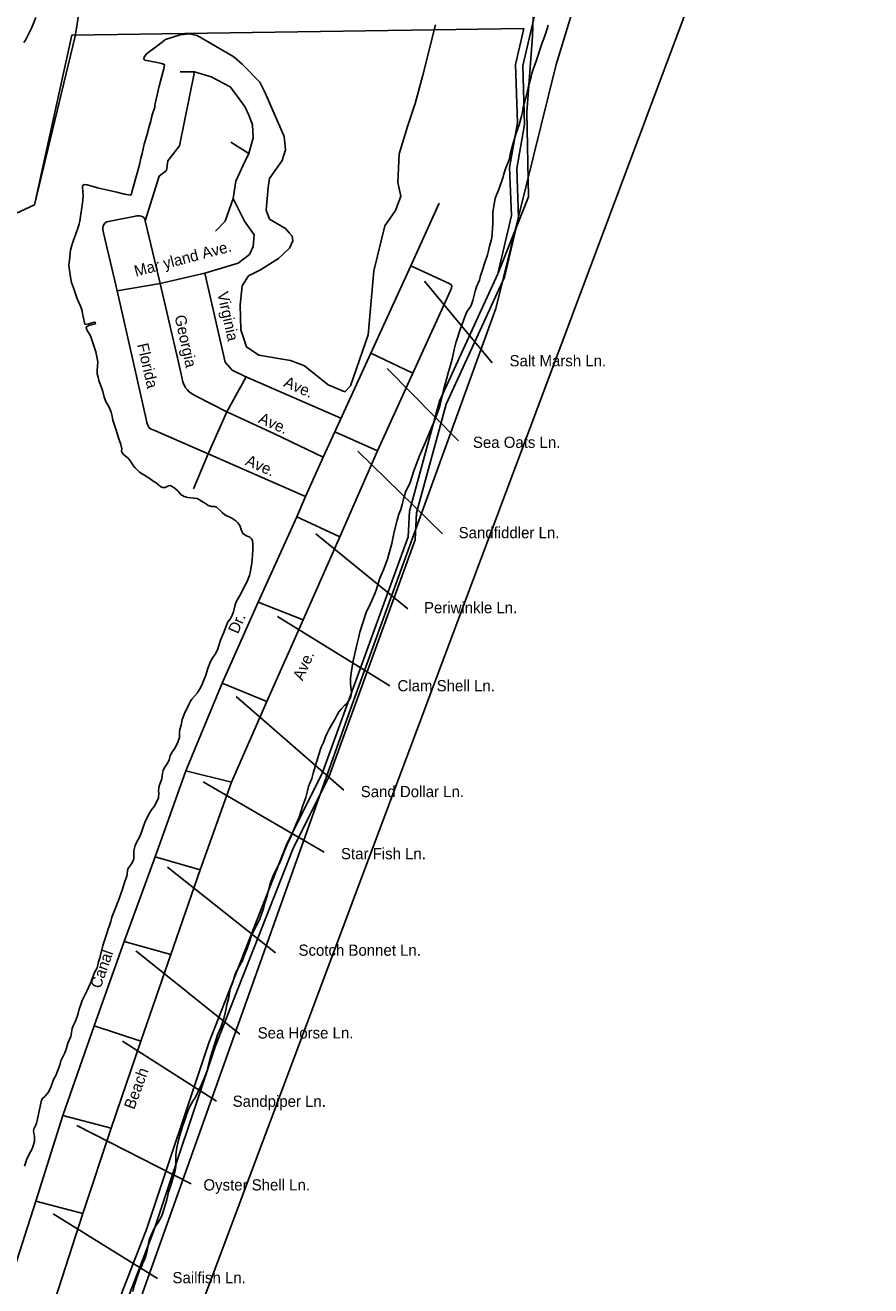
# Model space of a CAD drawing. Extents: x 1945482 to 2853149, y 66427 to 1015778.
# Drawn here: x 2336264 to 2341217, y 107724 to 115103 of the extents above; entities that cross this region are included whole.
import ezdxf

# ---------------------------------------------------------------- set-up
doc = ezdxf.new("R2010")
doc.units = 0
for name, color, linetype in [('Old_Level_10', 7, 'Continuous'), ('Old_Level_35', 7, 'Continuous'), ('Old_Level_48', 7, 'Continuous'), ('Old_Level_49', 7, 'Continuous'), ('Old_Level_52', 7, 'Continuous'), ('Old_Level_60', 7, 'Continuous'), ('Old_Level_61', 7, 'Continuous'), ('Old_Level_63', 7, 'Continuous')]:
    doc.layers.add(name, color=color, linetype=linetype)

msp = doc.modelspace()

# ---------------------------------------------------------------- linework, layer by layer
at = {"layer": 'Old_Level_10'}
for points in [[(2338998.7, 113127.3), (2338603.3, 113605.7)], [(2338801, 112671), (2338383.6, 113094.4)], [(2338707.6, 112126.7), (2338213.3, 112610.5)], [(2338504.4, 111686.9), (2337966.1, 112126.7)], [(2338400, 111236.1), (2337740.9, 111642.9)], [(2338130.7, 110624.6), (2337499.2, 111173.9)], [(2338015.4, 110262), (2337307, 110674)], [(2337729.8, 109674.2), (2337098.3, 110174.1)], [(2337521.2, 109196.3), (2336911.6, 109685.2)], [(2337383.9, 108805.1), (2336834.8, 109156.6)], [(2337235.6, 108321.7), (2336565.8, 108662.3)], [(2337038, 107767), (2336428.5, 108146)]]:
    msp.add_lwpolyline(points, dxfattribs=at)
at = {"layer": 'Old_Level_35'}
for p, q in [((2338689.3, 114062), (2338523, 113694.1)), ((2338523, 113694.1), (2338288.4, 113183.6)), ((2336802, 113548.3), (2337053.7, 113591.1)), ((2338076.8, 112723.3), (2338288.4, 113183.6)), ((2338288.4, 113183.6), (2338535.3, 113066.3)), ((2338328.4, 112611.8), (2338535.3, 113066.3)), ((2337336.2, 112593.6), (2337445.6, 112840.8)), ((2338076.8, 112723.3), (2338008.5, 112574.5)), ((2338076.8, 112723.3), (2338328.4, 112611.8)), ((2338107.3, 112109.4), (2338328.4, 112611.8)), ((2337250.1, 112388.7), (2337336.2, 112593.6)), ((2337905, 112345.3), (2337336.2, 112593.6)), ((2337905, 112345.3), (2338008.5, 112574.5)), ((2337854.3, 112224.8), (2337905, 112345.3)), ((2337629.4, 111726.2), (2337854.3, 112224.8)), ((2337854.3, 112224.8), (2338107.3, 112109.4)), ((2338107.3, 112109.4), (2337892.5, 111623.1)), ((2337418.1, 111251.8), (2337629.4, 111726.2)), ((2337629.4, 111726.2), (2337892.5, 111623.1)), ((2337892.5, 111623.1), (2337679.6, 111144.6)), ((2337205.7, 110737.7), (2337418.1, 111251.8)), ((2337418.1, 111251.8), (2337679.6, 111144.6)), ((2337679.6, 111144.6), (2337472.1, 110672.4)), ((2337024.9, 110235.6), (2337205.7, 110737.7)), ((2337205.7, 110737.7), (2337472.1, 110672.4)), ((2337472.1, 110672.4), (2337289.6, 110158.4)), ((2336844, 109739.7), (2337024.9, 110235.6)), ((2337024.9, 110235.6), (2337289.6, 110158.4)), ((2337289.6, 110158.4), (2337116.7, 109664.5)), ((2336668.8, 109245.7), (2336844, 109739.7)), ((2336844, 109739.7), (2337116.7, 109664.5)), ((2337116.7, 109664.5), (2336942.2, 109156.4)), ((2336484.7, 108721.9), (2336668.8, 109245.7)), ((2336942.2, 109156.4), (2336668.8, 109245.7)), ((2336942.2, 109156.4), (2336767.3, 108646.7)), ((2336325.6, 108220), (2336484.7, 108721.9)), ((2336484.7, 108721.9), (2336767.3, 108646.7)), ((2336767.3, 108646.7), (2336602.6, 108146.9)), ((2336166.8, 107720.1), (2336325.6, 108220)), ((2336602.6, 108146.9), (2336325.6, 108220)), ((2336602.6, 108146.9), (2336439.8, 107646.8))]:
    msp.add_line(p, q, dxfattribs=at)
for points in [[(2337256.4, 114831), (2337167.3, 114398.1), (2337099.5, 114308.9), (2337091, 114253.8), (2337048.6, 114219.8), (2336966.3, 113957.5)], [(2337053.7, 113591.1), (2337315.8, 113651.1), (2337510.9, 113710.5), (2337578.7, 113761.5), (2337599.9, 113808.2), (2337604.2, 113876.1), (2337549, 113956.7), (2337481.2, 114088.3), (2337498.1, 114190.1), (2337540.6, 114283.5), (2337574.5, 114351.4), (2337599.9, 114444.8), (2337595.7, 114521.1), (2337574.5, 114576.3), (2337553.3, 114623), (2337506.6, 114686.7), (2337464.2, 114741.8), (2337353.9, 114801.3), (2337256.4, 114831), (2337171.6, 114831)], [(2337574.5, 114351.4), (2337468.5, 114419.3)], [(2337481.2, 114088.3), (2337434.5, 113956.7), (2337379.4, 113897.3)], [(2336802, 113548.3), (2336722.6, 113887.5), (2336718.2, 113907.7), (2336717.9, 113916.6), (2336720, 113927.5), (2336724, 113935.8), (2336731.8, 113945.7), (2336741.7, 113952.3), (2336919.5, 113987.5), (2336933.3, 113987.7), (2336943.6, 113985.9), (2336953.6, 113982), (2336958.3, 113978.2), (2336964, 113968), (2336966.3, 113957.5), (2337053.7, 113591.1)], [(2337315.8, 113651.1), (2337434.5, 113131.7), (2337476.9, 113085), (2337553.3, 113046.8)], [(2338535.3, 113066.3), (2338754.4, 113550.6), (2338761.1, 113564.9), (2338762.6, 113576.8), (2338756.3, 113586.4), (2338747.9, 113590.4), (2338523, 113694.1)], [(2337053.7, 113591.1), (2337160.5, 113138.1), (2337181.3, 113042.1), (2337187.6, 113016.1), (2337191.7, 113004.1), (2337198.2, 112990.2), (2337203.8, 112981.3), (2337212.1, 112970.4), (2337225.1, 112957.5), (2337244.3, 112942.8), (2337264.5, 112931.2), (2337445.6, 112840.8)], [(2337336.2, 112593.6), (2337026.7, 112728.5), (2337008.6, 112736.3), (2336998.9, 112741.5), (2336990.8, 112747.4), (2336986.3, 112754.1), (2336980.2, 112766), (2336976.1, 112778), (2336972.4, 112796.9), (2336887.8, 113169), (2336802, 113548.3)], [(2337445.6, 112840.8), (2337558.4, 113044.5)], [(2337553.3, 113046.8), (2338113.1, 112802.2)], [(2337445.6, 112840.8), (2337725.1, 112711.7), (2338008.5, 112574.5)]]:
    msp.add_lwpolyline(points, dxfattribs=at)
at = {"layer": 'Old_Level_48'}
for points in [[(2334660.6, 113382.2), (2335533.7, 113689.2), (2336319, 114052.8), (2336537.9, 115045.8), (2339183.9, 115083.5)], [(2339183.9, 115083.5), (2339135, 114873.3), (2339147.1, 114532.4), (2339100.2, 114271.3), (2339112.1, 113989.4), (2339032.1, 113648.2), (2338690.1, 112902.8), (2338514.1, 112259.1), (2338507.1, 112107.8), (2338005, 110729.2), (2337793.2, 110300.7), (2337339.2, 109147.1)], [(2337339.2, 109147.1), (2336976, 108059.5), (2336830, 107682.8), (2336669.1, 107164.5), (2335564, 103786.1), (2335393, 103428.2), (2334965.1, 102180.4), (2334744.9, 101485.2)]]:
    msp.add_lwpolyline(points, dxfattribs=at)
at = {"layer": 'Old_Level_49'}
for points in [[(2336580.4, 115183.5), (2339245, 115328.5), (2339235.7, 115038.5), (2339203, 114594.1), (2339212.3, 114098.3), (2339032.1, 113648.2), (2338690.1, 112902.8), (2338514.1, 112259.1), (2338507.1, 112107.8), (2338005, 110729.2), (2337793.2, 110300.7), (2337339.2, 109147.1)], [(2334989.1, 113572), (2335533.7, 113689.2), (2336319, 114052.8), (2336557, 115038.5), (2336580.4, 115183.5)], [(2337339.2, 109147.1), (2336976, 108059.5), (2336830, 107682.8), (2336669.1, 107164.5), (2335564, 103786.1), (2335393, 103428.2), (2334965.1, 102180.4), (2334736.2, 101306.7)]]:
    msp.add_lwpolyline(points, dxfattribs=at)
at = {"layer": 'Old_Level_52'}
msp.add_lwpolyline([(2332774.3, 94909.4), (2333577.6, 97883.8), (2334423, 100131.9), (2335251.5, 102714.6), (2335953.9, 104717.9), (2336921.3, 107598.4), (2338178.9, 111127.7), (2339020, 113445.2), (2339373.3, 114873.2), (2339983.2, 116868.4), (2341036.1, 119166.1)], dxfattribs=at)
at = {"layer": 'Old_Level_60'}
for points in [[(2336327.2, 115147.7), (2336303.5, 115090.5), (2336274, 115031.4), (2336265.5, 115015.8), (2336256.2, 115002.1)], [(2338667.2, 115105.9), (2338591, 114803.5), (2338548.5, 114644.4), (2338506, 114517.1), (2338455.2, 114350), (2338446.7, 114182.9), (2338463.7, 114103.3), (2338433, 114017.8), (2338370.2, 113928.3), (2338306.7, 113665.7), (2338272.7, 113291.8), (2338169.7, 112991.4), (2338137, 112957.6), (2338038.2, 112997.4), (2337899.5, 113108.8), (2337817.7, 113140.6), (2337633.2, 113172.4), (2337560, 113220.2), (2337527, 113319.6), (2337522.7, 113466.8), (2337534.5, 113578.2), (2337571.7, 113635.9), (2337641.7, 113671.7), (2337746.7, 113737.3), (2337811.2, 113799), (2337831.5, 113840.8), (2337828.2, 113868.6), (2337812.5, 113886.5), (2337789, 113912.4), (2337695.7, 113968.1), (2337674.5, 114019.8), (2337687.2, 114153.1), (2337695.7, 114206.8), (2337770, 114312.2), (2337789, 114373.9), (2337780.5, 114451.4), (2337670.2, 114708), (2337638.5, 114769.7), (2337534.5, 114875.1), (2337485.7, 114918.9), (2337271.5, 115042.2), (2337224.7, 115052.1), (2337171.7, 115046.2), (2337085, 115020.1), (2337080.2, 115016.1), (2337066.5, 115003.5), (2337011.2, 114962.5), (2336989.5, 114947.9), (2336973.2, 114933.2), (2336961, 114915.3), (2336958.5, 114909.3), (2336960, 114903.3), (2336965, 114898.8), (2337037.7, 114884.5), (2337062.7, 114878.7), (2337079.2, 114873.4), (2337076, 114848.6), (2337071.5, 114833.6), (2337049.7, 114746.9), (2337031.7, 114669.5), (2337027, 114653.8), (2337024, 114636.4), (2337023, 114622.7), (2337010, 114584.2), (2337002, 114556.1), (2336999, 114540.9), (2336994.7, 114525), (2336989.7, 114510), (2336976, 114458.2), (2336961.2, 114406.8), (2336949.5, 114352), (2336941.5, 114324.3)], [(2338879, 113469.3), (2338886.7, 113490.9), (2338899, 113545.9), (2338908, 113571.3), (2338916, 113588.5), (2338924, 113611.6), (2338931.5, 113638.1), (2338940.5, 113663.5), (2338952.2, 113702.4), (2338971, 113758.7), (2338976.7, 113783), (2338984, 113809.1), (2338994.2, 113842.2), (2338997.5, 113860.9), (2339002.5, 113939.6), (2339003, 114008.6), (2339016.5, 114088.7), (2339021.7, 114105.4), (2339035.5, 114136.8), (2339041.7, 114153.3), (2339061, 114209.8), (2339071, 114244.6), (2339079.5, 114268.6), (2339089.7, 114292.6), (2339100.5, 114321), (2339104.7, 114346.9), (2339118, 114398.9), (2339140, 114470.9), (2339147, 114492.3), (2339157.5, 114519.7), (2339171.2, 114571.5), (2339176.7, 114594.7), (2339180.2, 114621.9), (2339182.7, 114631.6), (2339188.5, 114648.1), (2339192.2, 114665.1), (2339209, 114724.2), (2339212.7, 114746), (2339223.2, 114784.7), (2339232, 114820.8), (2339237.5, 114839.6), (2339256.7, 114892.9), (2339291.2, 115000), (2339305.5, 115035), (2339320.5, 115082.5), (2339327.7, 115104.3)], [(2336941.5, 114324.3), (2336934.5, 114288.2), (2336919.7, 114238), (2336891, 114133.1), (2336886, 114116.3), (2336882.2, 114109), (2336846.5, 114114.9), (2336800.2, 114126.3), (2336713, 114145), (2336688.5, 114150.9), (2336627.5, 114168.6), (2336612, 114170), (2336602.2, 114165.3), (2336599.5, 114155.5), (2336602.2, 114129.5), (2336603, 114106.7), (2336602, 114081.3), (2336598.7, 114048.4), (2336589.5, 113996.9), (2336583.5, 113957.1), (2336580.2, 113941.6), (2336576, 113927.1), (2336559, 113877.1), (2336546.5, 113846), (2336541.7, 113827.8), (2336534.5, 113808.9), (2336529.5, 113786.3), (2336527, 113771.1), (2336525, 113745.3), (2336520, 113699.3), (2336520.7, 113682.4), (2336531.5, 113616.4), (2336536.2, 113598.1), (2336547.7, 113566), (2336568.5, 113502.5), (2336587, 113459.2), (2336595, 113436.6), (2336597.7, 113431.5), (2336599, 113415.4), (2336610.7, 113361.7), (2336615.7, 113351.8), (2336637.5, 113355.2), (2336670.7, 113364.5), (2336674.5, 113363.5), (2336676.2, 113355.8), (2336637.2, 113345.7), (2336623, 113338.6), (2336620.7, 113334.6), (2336625, 113320), (2336645.7, 113284.3), (2336678.5, 113191.4), (2336686.5, 113153.3), (2336688.7, 113132.6), (2336685, 113081.4), (2336686.2, 113063.5), (2336690.5, 113042.7), (2336696, 113024.4), (2336713.5, 112976.7), (2336718.7, 112959.2), (2336725.7, 112926.1), (2336735.7, 112899.7), (2336754, 112872.1), (2336766.7, 112838), (2336771.5, 112822.2), (2336778, 112792), (2336783.5, 112773.8), (2336794.5, 112739.4), (2336801.7, 112719.7), (2336813.2, 112682.2), (2336825, 112648.4), (2336829.2, 112623.3), (2336827.5, 112612.4), (2336830.5, 112601.7), (2336841.5, 112589.2), (2336866.7, 112568.4), (2336878, 112553.7), (2336897.7, 112523.9), (2336907.7, 112511.8), (2336934, 112486.6), (2336990.2, 112452.3), (2337018.5, 112431.2), (2337030.5, 112424.8), (2337057.7, 112401.3), (2337070.5, 112396.8), (2337083.7, 112397.1), (2337104.2, 112407.5), (2337113, 112408.2), (2337134.2, 112396.8), (2337158.2, 112377.4), (2337176.5, 112356.8), (2337194.5, 112345.1), (2337217, 112337.8), (2337270.5, 112332.6), (2337288.7, 112323.8), (2337302.5, 112314.2), (2337323.7, 112301.2), (2337336, 112291), (2337355.5, 112285.7)], [(2337476, 109492.2), (2337482.2, 109510.2), (2337489.5, 109534.8), (2337498, 109557.3), (2337507.2, 109576), (2337528.2, 109614.1), (2337534.5, 109622.6), (2337548.5, 109660.7), (2337565, 109698.8), (2337578.5, 109737.6), (2337588, 109768.8), (2337602.7, 109803.2), (2337630.5, 109854.2), (2337638.5, 109872.3), (2337660, 109932), (2337668.5, 109964.8), (2337684.2, 110015.5), (2337697.7, 110070.6), (2337704.5, 110093.8), (2337711.7, 110113.5), (2337718.5, 110130), (2337739.7, 110173), (2337756.5, 110204.8), (2337765.7, 110225.3), (2337786.5, 110280.4), (2337798.2, 110307.9), (2337819.2, 110352), (2337851.2, 110429.2), (2337868.5, 110466.5), (2337890.5, 110535.5), (2337907, 110582.2), (2337919, 110629.6), (2337924, 110646.4), (2337943, 110694.7), (2337951, 110725.8), (2337983.2, 110835.1), (2337998.5, 110878.1), (2338010.7, 110904.8), (2338023.5, 110938), (2338032.7, 110958.7), (2338046.5, 110985.5), (2338079, 111043), (2338091, 111066.8), (2338101.7, 111083.7), (2338115.5, 111100.3), (2338136.5, 111122.1), (2338148.2, 111133), (2338163.5, 111156.2), (2338171.2, 111173.6), (2338174.5, 111194.6), (2338169.5, 111248.5), (2338170, 111279.4), (2338173.5, 111309.8), (2338185.2, 111382.6), (2338192, 111415.9), (2338206.7, 111475.8), (2338215.5, 111514.9), (2338224.7, 111550), (2338261.2, 111665), (2338286.2, 111717.8), (2338309.5, 111770.9), (2338319.2, 111796.9), (2338341.5, 111865.6), (2338363, 111916), (2338377.2, 111952.5), (2338385.7, 111977.8), (2338411.5, 112069), (2338418.7, 112108.4), (2338425.2, 112137.9), (2338443, 112206.8), (2338453.2, 112240.4), (2338463.5, 112268.6), (2338471.7, 112297.5), (2338481, 112337.7), (2338492.2, 112370.1), (2338518.2, 112426.6), (2338540.7, 112495.1), (2338575, 112587.7), (2338602.5, 112649.2), (2338646.2, 112752.3), (2338658.2, 112778.3), (2338688, 112861.3), (2338696.2, 112890.4), (2338705.5, 112931.3), (2338714.7, 112967.4), (2338744, 113074.2), (2338756, 113113.6), (2338764.5, 113148.2), (2338776, 113205), (2338786.7, 113243.3), (2338813, 113327.8), (2338830, 113369.8), (2338830.5, 113374.1), (2338844.5, 113411.1), (2338852.7, 113429.6), (2338871.5, 113455.6), (2338879, 113469.3)], [(2337355.5, 112285.7), (2337372.5, 112285.2), (2337384.2, 112282.2), (2337402.7, 112266.4), (2337417.2, 112250.6), (2337432.5, 112237.6), (2337475, 112218.2), (2337497.5, 112203), (2337509.7, 112191.2), (2337521, 112174.7), (2337528.7, 112150.7), (2337539.5, 112128.8), (2337561, 112114.8), (2337579, 112105.7), (2337589, 112096.7), (2337594.5, 112087.4), (2337597.2, 112066), (2337597, 112035.1), (2337593.5, 111970.9), (2337590.5, 111943.4), (2337582.5, 111897.7), (2337578.5, 111882.1), (2337561.5, 111842.6), (2337544.5, 111811.6), (2337524.7, 111771.6), (2337502, 111732.4), (2337494.7, 111710.6), (2337483.2, 111669.7), (2337471.5, 111640.9), (2337463, 111625.3), (2337451, 111611.1), (2337426.5, 111545.4), (2337408.7, 111504.3), (2337390.2, 111446.7), (2337377.5, 111420.7), (2337362.7, 111401.2), (2337350.2, 111378.1), (2337334.7, 111337.6), (2337320, 111292.9), (2337307.5, 111265.8), (2337298.5, 111240.9), (2337286.5, 111217.7), (2337271.5, 111193.2), (2337240.5, 111158.2), (2337232.2, 111145.6), (2337221.5, 111122.6), (2337212, 111105.7), (2337201.5, 111084), (2337184.2, 111038.7), (2337177.5, 111005.9), (2337170.2, 110981.1), (2337167.5, 110966.6), (2337168, 110950.3), (2337167, 110933.8), (2337158.2, 110907.1)], [(2337158.2, 110907.1), (2337144.2, 110877.7), (2337136.2, 110864.9), (2337126.7, 110852.2), (2337114, 110828.9), (2337107.5, 110800.7), (2337094, 110777.4), (2337077.7, 110753.9), (2337071.2, 110741), (2337067.5, 110725.2), (2337063.5, 110691.8), (2337059, 110676.2), (2337048.2, 110650.2), (2337045.7, 110623.5), (2337046.5, 110607.9), (2337044.5, 110581.4), (2337027.2, 110543.3), (2337019.2, 110530.2), (2337003.2, 110511.2), (2336991.2, 110489.9), (2336967.7, 110442.1), (2336938, 110358.4), (2336914, 110314.8), (2336908, 110300.8), (2336903.5, 110286), (2336901.2, 110270.2), (2336899.7, 110223.5), (2336890.7, 110199.3), (2336876, 110180.6), (2336865.7, 110164.9), (2336859, 110123), (2336848.2, 110091.7), (2336832.2, 110039.9), (2336826.7, 110025.4), (2336819.2, 110001.9), (2336795.7, 109941.3), (2336787, 109921), (2336772.2, 109881.7), (2336765, 109856.2), (2336757.7, 109834.2), (2336750.2, 109814.7), (2336744.5, 109792.1), (2336719, 109717.1), (2336701, 109643.2), (2336694.5, 109626.4), (2336693, 109620.5), (2336686, 109585.6), (2336670.5, 109557.2), (2336664, 109543.2), (2336645.7, 109496.1), (2336625.5, 109448.3), (2336607.5, 109414.6), (2336598, 109395.1), (2336589.2, 109370.3), (2336580.7, 109343.2), (2336574, 109317.7), (2336566, 109294.2), (2336556.5, 109268.5), (2336545, 109246.5), (2336539.7, 109230.6), (2336532.2, 109183), (2336514.2, 109144.2), (2336506, 109115.3), (2336496, 109087.5), (2336480, 109056.6), (2336473.2, 109040.9), (2336466, 109016.3), (2336443.2, 108956.1), (2336430.2, 108931.7), (2336412.5, 108881.1), (2336399, 108855.7), (2336380.7, 108834), (2336365.5, 108821), (2336359.7, 108810.2), (2336334.7, 108691.8), (2336330, 108675.6), (2336324.2, 108660.9), (2336316.5, 108646.6), (2336313, 108630.4), (2336315.5, 108615), (2336319.2, 108600.2), (2336318, 108568.5), (2336308.5, 108537.1), (2336302, 108522.1), (2336294.2, 108508.3), (2336276, 108470.9), (2336259.5, 108424.4)], [(2336894.5, 107690.2), (2336905.2, 107729.9), (2336919.5, 107776.3), (2336936.2, 107820.8), (2336946.5, 107839.9), (2336953, 107859.1), (2336961, 107871.9), (2336967, 107887.8), (2336976, 107920.2), (2336980.5, 107939.7), (2336984, 107962.9), (2336988.2, 107983.3), (2336993, 107999.7), (2337022.2, 108063.2), (2337033, 108081.1), (2337043.5, 108095.6), (2337059.7, 108126.4), (2337068, 108145.2), (2337093, 108227.3), (2337104, 108271.6), (2337116.7, 108310.7), (2337143, 108399.6), (2337145.7, 108422), (2337145.7, 108471.1), (2337146.7, 108488.7), (2337148.5, 108506.5), (2337152.5, 108533.7), (2337157.5, 108560), (2337163.7, 108583.7), (2337170, 108603.4), (2337176.7, 108631), (2337184.5, 108656.6), (2337219, 108751.7), (2337228.5, 108773.1), (2337238, 108792), (2337248, 108808.2), (2337259.5, 108824.8), (2337275, 108857.9), (2337297.5, 108902.3), (2337316.2, 108948.2), (2337330, 108984.7), (2337334.7, 109000.7), (2337346, 109048.1), (2337356.7, 109088.7), (2337373.7, 109136.4), (2337390.7, 109193.3), (2337410.5, 109236), (2337426.7, 109288), (2337439.5, 109338.1), (2337445.5, 109371.4), (2337454, 109403.9), (2337465.5, 109460.9), (2337469.7, 109477.2), (2337476, 109492.2)]]:
    msp.add_lwpolyline(points, dxfattribs=at)
at = {"layer": 'Old_Level_61'}
msp.add_lwpolyline([(2333354.1, 96950.2), (2335005.7, 102164.1), (2335432.9, 103409.2), (2335602.9, 103765.1), (2336709.7, 107148.2), (2336870.5, 107665.8), (2337016.1, 108041.2), (2337379.2, 109129.5), (2337832.4, 110280.6), (2338043.6, 110707.6), (2338547.4, 112090.2), (2338556.6, 112248.9), (2338730.5, 112885.1), (2339071.1, 113627.6), (2339153.7, 113976.3), (2339143.1, 114264.6), (2339189, 114521.3), (2339178.1, 114865.4), (2339821.4, 117630.5), (2340329.7, 119005.6), (2340846, 120123.9), (2340849.5, 120157.7), (2340856.7, 120177), (2340881.5, 120453.6)], dxfattribs=at)
at = {"layer": 'Old_Level_63'}
msp.add_lwpolyline([(2336452.5, 105360.7), (2340329.8, 115709.4), (2347995, 148689.9)], dxfattribs=at)

# ---------------------------------------------------------------- texts
at = {"layer": 'Old_Level_10'}
for s, height, rotation, p in [('Mar yland Ave.', 65.617, 14.80448, (2336912.2, 113630.7)), ('Virginia', 65.62, 282.46835, (2337388.3, 113535.4)), ('Georgia', 65.62, 282.45654, (2337138.3, 113399.3)), ('Florida', 65.62, 282.98416, (2336919.4, 113234)), ('Ave.', 65.62, 336.0724, (2337773.1, 112991)), ('Ave.', 65.62, 336.0724, (2337625.4, 112778.8)), ('Ave.', 65.62, 336.0724, (2337548.5, 112531.4)), ('Dr.', 65.62, 66.45804, (2337510.2, 111536.4)), ('Ave.', 65.62, 66.32998, (2337889, 111262.6)), ('Canal', 65.62, 70.63444, (2336704.7, 109459.4)), ('Beach', 65.62, 69.84386, (2336902.1, 108752))]:
    msp.add_text(s, height=height, rotation=rotation, dxfattribs=at).set_placement(p)
for s, p in [('Salt Marsh Ln.', (2339100.9, 113106.5)), ('Sea Oats Ln.', (2338886.4, 112629.1)), ('Sandfiddler Ln.', (2338802.8, 112100.4)), ('Periwinkle Ln.', (2338599.9, 111661.4)), ('Clam Shell Ln.', (2338444.8, 111204.2)), ('Sand Dollar Ln.', (2338229.4, 110584.6)), ('Star Fish Ln.', (2338113.7, 110221.2)), ('Scotch Bonnet Ln.', (2337864.8, 109656.2)), ('Sea Horse Ln.', (2337625.6, 109172)), ('Sandpiper Ln.', (2337479.2, 108771.8)), ('Oyster Shell Ln.', (2337307.9, 108282.2)), ('Sailfish Ln.', (2337126.9, 107739.2))]:
    msp.add_text(s, height=65.617, dxfattribs=at).set_placement(p)

doc.saveas('drawing.dxf')
